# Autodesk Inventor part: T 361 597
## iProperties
Company: Mayer & Müller AG Schaltgeräte
Shininess: 64.0
Length Units: 11269
Angle Units: 11279
Time Units: 11290
Mass Units: 11283
Length Display Precision: 3
Angle Display Precision: 2
Compacted: True
Part Number: T 361 597
Document SubType Name: Modeling
Created: 2006-10
Material: 1.4301
Designer: cad4
Manufacturer: Standard
Standards Organization: Custom
Description: Gewindeplatte
Density: 7.86 g/cm^3
Density: 0.0
Volumn: 0.0
Area: 0.0
PropertySet Name: Model Information
Control State: 0
Master: False
Checked Out: False
Zweck: Isolator - HN / HE 2000 DC
Revision Number: 361597
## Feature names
1. Extrusion1
2. Bohrung_M10 [Hole]
3. Fase2 [Chamfer]
